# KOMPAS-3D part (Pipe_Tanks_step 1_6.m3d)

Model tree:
1. X Axis
2. Y Axis
3. Z Axis  (labels: T-Bend Dn 50; Pipe Dn 50; C:\Program Files\ASCON\KOMPAS-3D V10\Sys\graphic.lyt; Pipe_Tanks_step 1_6.m3d)
     Òîëùèíà ñòåíêè 1 = 1

Referenced files in C:\Documents and Settings\kashirsky\Мои документы\Camtasia Studio\Pipelines3D\Tanks\: Tanks_step 1.a3d, Tanks_step 1.spw
Referenced files in C:\Documents and Settings\kashirsky\Мои документы\Camtasia Studio\Pipelines3D\Tanks\Tanks_step 1_Pipes\: Pipe_Tanks_step 1_6.m3d
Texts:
  Pipe Dn 50
  Steel ASTM A295
  Three Point Plane
  Plane at Angle
  Line and Point Plane
  Axis through Two Vertices
  Axis of Feature
  Axis of Conical Surface
  Axis through Edge
  Trim by Surface
  Trim by Sketch
  Feature with No History
  Intersection Axis of Two Planes
  Two Line Plane
  Line and Face Plane
  Bend by line
  Hole in sheet body
  Cut in sheet body
  Point in CM
  Linear Dimension from Line to Point
  Surface Finish Symbol
  Geometric Tolerance Symbol
  Leader #1
  Leader #2
  Leader #3
  Shape Deviations and Datum
  Node point number
  Mark of coordination axis
  Node point designation
  Mark/Reference designation with leader
  Mark/reference designation on line
  Mark/Reference designation without leader
  T-Bend Dn 50
  Plane of section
